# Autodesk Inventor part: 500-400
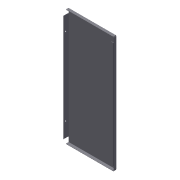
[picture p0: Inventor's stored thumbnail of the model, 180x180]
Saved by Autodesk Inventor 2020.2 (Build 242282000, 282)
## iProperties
Created: 2010-10
Part Number: 500-400
Material: St1203
Document SubType Name: Konstrukcje blachowe
Designer: F.Stasiak
Density: 7.85 g/cm^3
Sheet Metal Rule: Blacha stalowa 2.5 mm/Okrągły
Description: =Wieniec górny <DŁUGOŚĆ> x <SZEROKOŚĆ>
Appearance: Metal-Stal
Company: Fabian Stasiak CAD Consulting
Manager: www.cadconsulting.pl
DŁUGOŚĆ: 1200
SZEROKOŚĆ: 500
Author: F.Stasiak
Subject: Zbiór ćwiczeń. Autodesk Inventor 2020. Kurs podstawowy
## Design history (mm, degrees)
node "Powierzchnia1"
  sketch "Szkic2"
    geometry: L1 (-248.75, -597.5)-(248.75, -597.5); L2 (248.75, -597.5)-(248.75, 597.5); L3 (248.75, 597.5)-(-248.75, 597.5); L4 (-248.75, 597.5)-(-248.75, -597.5); 3 further points
    constraints: 8 end point, 2 midpoint, 2 parallel, 1 horizontal, 1 horizontal alignment, 1 perpendicular, 1 vertical alignment
    dimensions: "d0" = 497.5 distance of L3.end L2.end; "d1" = 1195 distance of L2.end L1.end
node "Kołnierz1"
node "Kołnierz2"
node "Kołnierz3"
sketch "Szkic6"
  geometry: L1 (1095, 45)-(0, 45) reference; L2 (0, 0)-(0, 45) reference; L3 (0, 0)-(1095, 0) reference; L4 (1095, 0)-(1095, 45) reference; L5 (0, 22.5)-(1095, 22.5); 3 further points
  constraints: 2 end point, 2 midpoint, 2 point on line
  dimensions: "d35" = 150 distance from line of point (150, 22.5) L2; "d36" = 150 distance from line of L4 point (945, 22.5) (= d35)
hole "Hole1" sketch "Szkic6" at (150, 22.5), (945, 22.5) diameter "d37" = 12; stored, may be unused: countersink angle "d41" = 90 deg, drill point angle "d43" = 118 deg; dims "d38" = 6, "d39" = 4, "d40" = 2, "d42" = 2.5 (= Grubość)
feature "Narożnik4" dims "d44" = 10 (= RozmiarPodcięciaNarożnika), "d45" = 2.5 (= PromieńGięcia), "d46" = 2.5 (= Wielk_odstępu), "d47" = 0, "d48" = 10, "d73" = 2.5 (= Grubość)
feature "Narożnik5" dims "d49" = 10 (= RozmiarPodcięciaNarożnika), "d50" = 2.5 (= PromieńGięcia), "d51" = 2.5 (= Wielk_odstępu), "d52" = 0, "d53" = 10, "d73" = 2.5 (= Grubość)
node "Kołnierz4"
feature "Zawinięcie obrzeża1" dims "d66" = 2.5 (= SzerokośćGięciaPodcięcia), "d67" = 1.25 (= GłębokośćGięciaPodcięcia), "d68" = 5 (= MinimalnaPozostałość), "d69" = 2.5 (= PromieńGięcia), "d70" = 10 (= 4 x Grubość), "d71" = 1.25 (= 0.5 x Grubość), "d72" = 0.625 (= 0.5 x d71), "d73" = 2.5 (= Grubość), "OdstępPołączenia" = 0.01
node "Bryła1"
feature "Płyta1" dims "d73" = 2.5 (= Grubość)
sketch "Szkic3"
  geometry: L1 (-30, 0)-(-30, -1195); L2 (-30, -1195)-(0, -1195); 1 other entity
  constraints: 4 end point, 4 other
feature "Płyta2" dims "d3" = 2.5 (= SzerokośćGięciaPodcięcia), "d4" = 1.25 (= GłębokośćGięciaPodcięcia), "d5" = 5 (= MinimalnaPozostałość), "d6" = 2.5 (= PromieńGięcia), "d7" = 30, "d8" = 90 deg, "d9" = 2.5 (= PromieńGięcia), "d10" = 10 (= RozmiarPodcięciaNarożnika), "d11" = 2.5 (= Wielk_odstępu), "d12" = 2.5 (= Rozmiar_promienia_Jacobiego), "d73" = 2.5 (= Grubość), "OdstępPołączenia" = 0.01
feature "Gięcie1" dims "d3" = 2.5 (= SzerokośćGięciaPodcięcia), "d4" = 1.25 (= GłębokośćGięciaPodcięcia), "d5" = 5 (= MinimalnaPozostałość), "d6" = 2.5 (= PromieńGięcia), "d7" = 30, "d8" = 90 deg, "d9" = 2.5 (= PromieńGięcia), "d73" = 2.5 (= Grubość), "OdstępPołączenia" = 0.01
feature "Narożnik1" dims "d7" = 30, "d8" = 90 deg, "d10" = 10 (= RozmiarPodcięciaNarożnika), "d11" = 2.5 (= Wielk_odstępu), "d12" = 2.5 (= Rozmiar_promienia_Jacobiego)
sketch "Szkic4"
  geometry: L1 (0, 1145)-(0, 50); L2 (0, 50)-(50, 50); L3 (50, 50)-(50, 1145); L4 (50, 1145)-(0, 1145)
  constraints: 8 end point
feature "Płyta3" dims "d13" = 2.5 (= SzerokośćGięciaPodcięcia), "d14" = 1.25 (= GłębokośćGięciaPodcięcia), "d15" = 100, "d16" = 2.5 (= PromieńGięcia), "d17" = 50, "d18" = 50, "d19" = 50, "d20" = 90 deg, "d21" = 2.5 (= PromieńGięcia), "d22" = 10 (= RozmiarPodcięciaNarożnika), "d23" = 2.5 (= Wielk_odstępu), "d24" = 2.5 (= Rozmiar_promienia_Jacobiego), "d73" = 2.5 (= Grubość), "OdstępPołączenia" = 0.01
feature "Gięcie2" dims "d13" = 2.5 (= SzerokośćGięciaPodcięcia), "d14" = 1.25 (= GłębokośćGięciaPodcięcia), "d15" = 100, "d16" = 2.5 (= PromieńGięcia), "d19" = 50, "d20" = 90 deg, "d21" = 2.5 (= PromieńGięcia), "d73" = 2.5 (= Grubość), "OdstępPołączenia" = 0.01
feature "Narożnik2" dims "d19" = 50, "d20" = 90 deg, "d22" = 10 (= RozmiarPodcięciaNarożnika), "d23" = 2.5 (= Wielk_odstępu), "d24" = 2.5 (= Rozmiar_promienia_Jacobiego)
sketch "Szkic5"
  geometry: L1 (0, -30)-(492.5, -30); L2 (492.5, -30)-(492.5, 0); 1 other entity
  constraints: 4 end point, 4 other
feature "Płyta4" dims "d25" = 2.5 (= SzerokośćGięciaPodcięcia), "d26" = 1.25 (= GłębokośćGięciaPodcięcia), "d27" = 5 (= MinimalnaPozostałość), "d28" = 2.5 (= PromieńGięcia), "d29" = 30, "d30" = 90 deg, "d31" = 2.5 (= PromieńGięcia), "d32" = 10 (= RozmiarPodcięciaNarożnika), "d33" = 2.5 (= Wielk_odstępu), "d34" = 2.5 (= Rozmiar_promienia_Jacobiego), "d73" = 2.5 (= Grubość), "OdstępPołączenia" = 0.01
feature "Gięcie3" dims "d25" = 2.5 (= SzerokośćGięciaPodcięcia), "d26" = 1.25 (= GłębokośćGięciaPodcięcia), "d27" = 5 (= MinimalnaPozostałość), "d28" = 2.5 (= PromieńGięcia), "d29" = 30, "d30" = 90 deg, "d31" = 2.5 (= PromieńGięcia), "d73" = 2.5 (= Grubość), "OdstępPołączenia" = 0.01
feature "Narożnik3" dims "d29" = 30, "d30" = 90 deg, "d32" = 10 (= RozmiarPodcięciaNarożnika), "d33" = 2.5 (= Wielk_odstępu), "d34" = 2.5 (= Rozmiar_promienia_Jacobiego)
node "Pętla rzutowana1"
sketch "Szkic7"
  geometry: L1 (0, -1141.464)-(0, -45); L2 (0, -45)-(-15, -45); L3 (-15, -45)-(-15, -1141.464); L4 (-15, -1141.464)-(0, -1141.464)
  constraints: 8 end point
feature "Płyta5" dims "d54" = 2.5 (= SzerokośćGięciaPodcięcia), "d55" = 1.25 (= GłębokośćGięciaPodcięcia), "d56" = 5 (= MinimalnaPozostałość), "d57" = 2.5 (= PromieńGięcia), "d58" = 45, "d59" = 45, "d60" = 20, "d61" = 90 deg, "d62" = 2.5 (= PromieńGięcia), "d63" = 10 (= RozmiarPodcięciaNarożnika), "d64" = 2.5 (= Wielk_odstępu), "d65" = 2.5 (= Rozmiar_promienia_Jacobiego), "d73" = 2.5 (= Grubość), "OdstępPołączenia" = 0.01
feature "Gięcie4" dims "d54" = 2.5 (= SzerokośćGięciaPodcięcia), "d55" = 1.25 (= GłębokośćGięciaPodcięcia), "d56" = 5 (= MinimalnaPozostałość), "d57" = 2.5 (= PromieńGięcia), "d60" = 20, "d61" = 90 deg, "d62" = 2.5 (= PromieńGięcia), "d73" = 2.5 (= Grubość), "OdstępPołączenia" = 0.01
feature "Narożnik6" dims "d60" = 20, "d61" = 90 deg, "d63" = 10 (= RozmiarPodcięciaNarożnika), "d64" = 2.5 (= Wielk_odstępu), "d65" = 2.5 (= Rozmiar_promienia_Jacobiego)
sketch "Szkic8"
  geometry: L1 (0, -2.5)-(0, 0); L2 (0, 1.25)-(-6.875, 1.25); L3 (-6.875, 1.25)-(-6.875, 3.75); L4 (-6.875, 3.75)-(0, 3.75); A1 r 0.625 centre (0, 0.625) between (0, 0) and (0, 1.25); A2 r 3.125 centre (0, 0.625) between (0, -2.5) and (0, 3.75)
  constraints: 8 end point, 4 point on circle
other parameters: "Grubość" = 2.5 (derived), "WspółczynnikK" = 4.4, "PromieńGięcia" = 2.5 (= Grubość), "SzerokośćGięciaPodcięcia" = 2.5 (= Grubość), "GłębokośćGięciaPodcięcia" = 1.25 (= 0.5 x Grubość), "MinimalnaPozostałość" = 5 (= 2 x Grubość), "PromieńPrzejścia" = 2.5 (= PromieńGięcia), "Rozmiar_promienia_Jacobiego" = 2.5 (= PromieńGięcia), "Wielk_odstępu" = 2.5 (= Grubość), "d2" = 2.5 (= PromieńGięcia)
